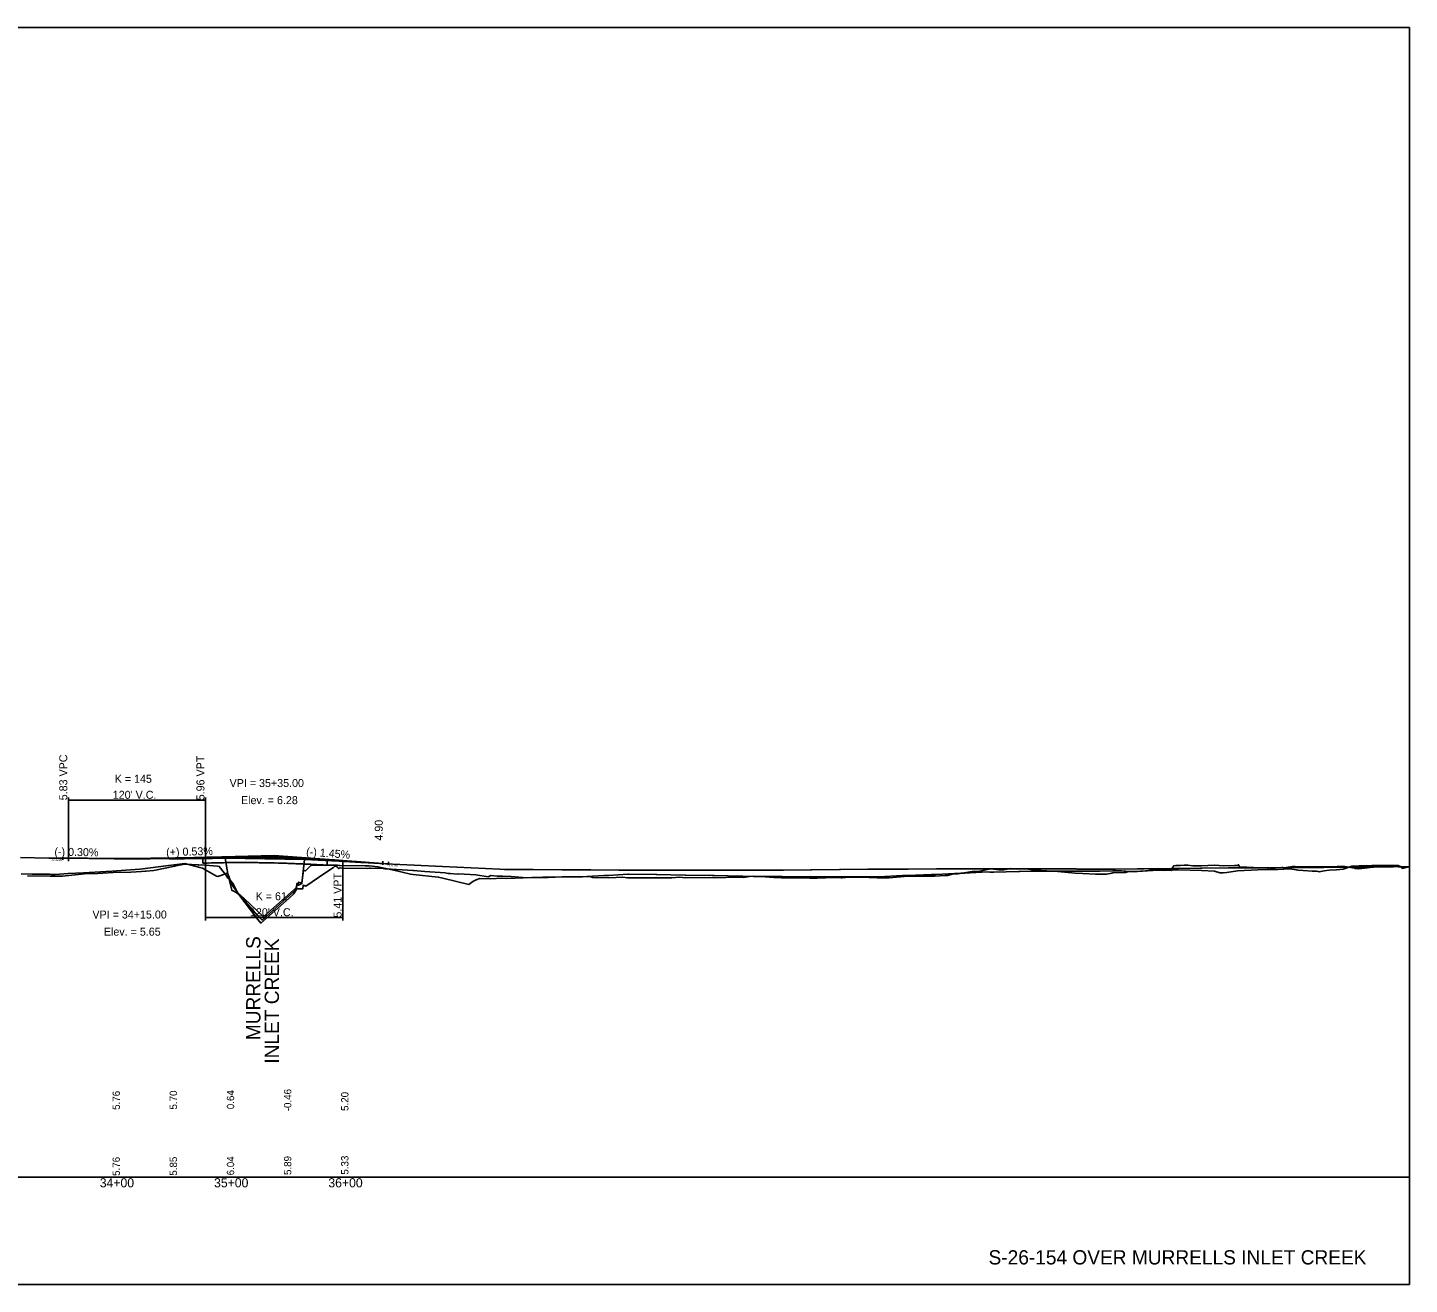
# Model space of a CAD drawing. Extents: x 2615579 to 2617675, y 643161 to 644261.
# Drawn here: x 2616466 to 2617675, y 643161 to 644261 of the extents above; entities that cross this region are included whole.
import ezdxf

# ---------------------------------------------------------------- set-up
doc = ezdxf.new("R2010")
doc.units = 0
for name, color, linetype in [('BR_CONCRETE', 7, 'Continuous'), ('BR_EXIST_GROUND_RT', 7, 'Continuous'), ('RD_EX_TX_Road_ELEV', 7, 'Continuous'), ('RD_PD_CstnLmt', 7, 'Continuous'), ('RD_PD_DR_ErosCtrl', 7, 'Continuous'), ('RD_PD_Final_TrvlWay', 7, 'Continuous'), ('RD_PD_PaveShd', 7, 'Continuous'), ('RD_PD_RW_TX', 7, 'Continuous'), ('RD_SHT_IplotShp', 7, 'Continuous'), ('RD_SHT_ShtClip', 7, 'Continuous'), ('RD_SHT_TX', 7, 'Continuous'), ('RD_Sketch8', 7, 'Continuous')]:
    doc.layers.add(name, color=color, linetype=linetype)

msp = doc.modelspace()

# ---------------------------------------------------------------- linework, layer by layer
at = {"layer": 'BR_CONCRETE'}
for p, q in [((2616619.3, 643529.3), (2616619.3, 643534.3)), ((2616728.2, 643527.5), (2616728.2, 643532.5))]:
    msp.add_line(p, q, dxfattribs=at)
msp.add_lwpolyline([(2616459.8, 643534.2), (2616484.8, 643533.7), (2616490, 643533.6), (2616514.6, 643533.5), (2616515, 643533.5), (2616539.4, 643533.3), (2616540, 643533.3), (2616564.3, 643533.2), (2616565, 643533.2), (2616565.6, 643533.2), (2616590, 643533.1), (2616602.4, 643533), (2616602.8, 643533), (2616603.4, 643533), (2616627.8, 643533.4), (2616633.8, 643533.5), (2616639, 643533.6), (2616640.6, 643523.4), (2616641.3, 643519.8), (2616643.5, 643513.6), (2616645.7, 643509.1), (2616649.5, 643504.3), (2616650.3, 643502.7), (2616667.6, 643483.1), (2616671.4, 643479.5), (2616692.6, 643498.5), (2616700.2, 643505.2), (2616700.5, 643506), (2616701.6, 643509.7), (2616703, 643510.1), (2616706.1, 643511.4), (2616708.4, 643532.5), (2616732.3, 643531.3), (2616733.3, 643531.2), (2616757.7, 643529.9), (2616758.3, 643529.9), (2616758.9, 643529.9), (2616779.3, 643528.8), (2616804.2, 643527.6), (2616829.2, 643526.4), (2616854.2, 643525.1), (2616879.1, 643523.9), (2616883.4, 643523.7), (2616888.4, 643523.7), (2616908.5, 643523.6), (2616933.6, 643523.5), (2616958.4, 643523.3), (2616958.8, 643523.3), (2616983.4, 643523.2), (2616991.3, 643523.2), (2617015.6, 643523.1), (2617016.3, 643523.1), (2617040.5, 643523.1), (2617041.3, 643523.1), (2617065.4, 643523), (2617066.3, 643523), (2617090.3, 643523), (2617091.3, 643523), (2617100.8, 643523), (2617101.3, 643523), (2617102.4, 643523), (2617126.3, 643523.2), (2617127.3, 643523.2), (2617151.3, 643523.4), (2617152.3, 643523.4), (2617176.3, 643523.7), (2617177.3, 643523.7), (2617201.3, 643523.9), (2617201.7, 643523.9), (2617211.4, 643524), (2617235.8, 643524.1), (2617236.4, 643524.1), (2617261.4, 643524.2), (2617266.4, 643524.2), (2617286.5, 643524.2), (2617307.9, 643524.2), (2617308.5, 643524.3), (2617309.1, 643524.3), (2617333.2, 643524.3), (2617334.1, 643524.3), (2617358.4, 643524.3), (2617359.4, 643524.2), (2617383.4, 643524.2), (2617384.5, 643524.1), (2617408.4, 643524.1), (2617408.7, 643524.1), (2617417.9, 643524.1), (2617437.2, 643524.3), (2617441.6, 643524.3), (2617442.9, 643524.3), (2617466.6, 643524.6), (2617467.9, 643524.6), (2617468.4, 643524.6), (2617492.2, 643524.9), (2617493.5, 643524.9), (2617516.9, 643525.1), (2617518.1, 643525.2), (2617524.9, 643525.2), (2617526.4, 643525.2), (2617549.9, 643525.3), (2617550.9, 643525.3), (2617574.8, 643525.4), (2617575.5, 643525.5), (2617599.8, 643525.6), (2617600.2, 643525.6), (2617625, 643525.7), (2617634, 643525.7), (2617636, 643525.7), (2617661, 643526.1), (2617675, 643526.3)], dxfattribs=at)
for points in [[(2616619.3, 643529.3), (2616619.5, 643529.3), (2616621.9, 643529.3)], [(2616621.9, 643529.3), (2616624.3, 643529.4), (2616626.7, 643529.4), (2616629.1, 643529.5), (2616631.5, 643529.5), (2616633.9, 643529.6), (2616636.3, 643529.6), (2616638.7, 643529.7), (2616641.1, 643529.7), (2616643.5, 643529.7), (2616645.9, 643529.7), (2616648.2, 643529.7), (2616650.6, 643529.7), (2616653, 643529.7), (2616655.4, 643529.7), (2616657.8, 643529.7), (2616660.2, 643529.7), (2616662.6, 643529.7), (2616665, 643529.7), (2616667.4, 643529.7), (2616669.8, 643529.6), (2616672.1, 643529.6), (2616674.5, 643529.6), (2616676.9, 643529.5), (2616679.3, 643529.5), (2616681.7, 643529.4), (2616684.1, 643529.4), (2616686.5, 643529.3), (2616688.9, 643529.2), (2616691.3, 643529.2), (2616693.7, 643529.1), (2616696, 643529), (2616698.4, 643528.9), (2616700.8, 643528.8), (2616703.2, 643528.7), (2616705.6, 643528.6), (2616708, 643528.5), (2616710.4, 643528.4), (2616712.8, 643528.3), (2616715.2, 643528.2), (2616717.6, 643528.1), (2616719.9, 643527.9), (2616722.3, 643527.8), (2616724.7, 643527.7), (2616727.1, 643527.5), (2616728.2, 643527.5)]]:
    msp.add_spline(points, degree=3, dxfattribs=at)
at = {"layer": 'BR_EXIST_GROUND_RT'}
msp.add_lwpolyline([(2616460.4, 643520), (2616470.1, 643519.7), (2616485.4, 643519.5), (2616487.1, 643519.4), (2616490.1, 643519.4), (2616501.6, 643520.1), (2616514.9, 643520.7), (2616534.7, 643522.1), (2616539.8, 643522.3), (2616564.4, 643524), (2616564.7, 643524.1), (2616589.4, 643527.1), (2616589.7, 643527.2), (2616603.5, 643528.9), (2616616.9, 643525.4), (2616619, 643524.9), (2616631.4, 643518), (2616632.5, 643517.7), (2616640, 643520.2), (2616641, 643520.9), (2616644.7, 643505.6), (2616649, 643503.4), (2616650.8, 643501.7), (2616667.5, 643479.8), (2616670.2, 643476.7), (2616694.8, 643498.5), (2616699, 643502.3), (2616699.3, 643503.1), (2616700.7, 643505.4), (2616702.5, 643507.1), (2616702.8, 643506.9), (2616704.4, 643506.9), (2616705.7, 643506.7), (2616706.9, 643506.9), (2616707.1, 643509.9), (2616709.5, 643509.2), (2616726, 643520.5), (2616733.6, 643525.5), (2616734.8, 643526.5), (2616736.2, 643526.4), (2616736.6, 643526), (2616737.4, 643525.4), (2616737.9, 643524.8), (2616738.3, 643524.6), (2616738.6, 643524.6), (2616739.4, 643525.3), (2616740.9, 643525), (2616763.7, 643524.7), (2616765.2, 643524.9), (2616766, 643524.9), (2616777.3, 643524.7), (2616778.7, 643524.4), (2616779.4, 643524.4), (2616803.2, 643522.8), (2616803.7, 643522.8), (2616813.6, 643522.1), (2616831.4, 643520.7), (2616832.6, 643520.5), (2616834, 643520.3), (2616835.8, 643520.3), (2616842, 643519.7), (2616843.1, 643519.8), (2616858.2, 643519), (2616868.9, 643517.3), (2616871.5, 643518.6), (2616877, 643518), (2616881.6, 643517.8), (2616889.1, 643517.5), (2616902.5, 643516.3), (2616921.5, 643516.7), (2616927.6, 643517), (2616933.6, 643517.2), (2616951.7, 643517.3), (2616958.3, 643517.7), (2616960.7, 643516.8), (2616974.6, 643516.4), (2616981.1, 643516.8), (2616986.7, 643517), (2616991, 643516.5), (2616999.9, 643516.4), (2617014.8, 643516.4), (2617015.5, 643516.4), (2617029.8, 643516.5), (2617036.4, 643516.9), (2617041.8, 643516.3), (2617062.4, 643516.6), (2617066.9, 643516.5), (2617087.3, 643516.9), (2617092.4, 643516.8), (2617097.6, 643517.7), (2617100.9, 643517.8), (2617107.7, 643517.7), (2617119, 643516.7), (2617125.6, 643516.5), (2617131.2, 643516.4), (2617150.5, 643516.1), (2617156.8, 643516), (2617171.5, 643516.6), (2617177.9, 643516.5), (2617178.7, 643516.5), (2617184.5, 643517), (2617202.5, 643516.7), (2617203.5, 643516.7), (2617209.5, 643516.3), (2617211.7, 643516.4), (2617219.9, 643516.4), (2617233.1, 643517.5), (2617239.8, 643517.9), (2617258.3, 643517.8), (2617259.4, 643517.9), (2617269, 643518.4), (2617271, 643518.4), (2617276.3, 643519.9), (2617280.3, 643520), (2617294.3, 643522.2), (2617296.6, 643522.1), (2617299, 643522.3), (2617308.7, 643524.3), (2617315.9, 643523.3), (2617320.1, 643523.4), (2617326.3, 643524.7), (2617331.5, 643523.9), (2617338.6, 643524.2), (2617355.9, 643522.4), (2617357.9, 643522.5), (2617367.5, 643522.1), (2617382.7, 643520.6), (2617389, 643520.1), (2617400.4, 643519.6), (2617406.1, 643519.5), (2617409.9, 643519.5), (2617414.7, 643520.6), (2617415.5, 643520.7), (2617425.1, 643521.1), (2617426.7, 643521.1), (2617427.5, 643521.4), (2617429.9, 643521.9), (2617434, 643522), (2617437.2, 643522.1), (2617439.8, 643522.3), (2617440.7, 643522.2), (2617444.2, 643522.6), (2617449.5, 643523.4), (2617455.3, 643523), (2617460.1, 643522.9), (2617466.1, 643523), (2617466.8, 643522.8), (2617468.2, 643525.8), (2617468.8, 643527), (2617470.7, 643527.1), (2617473.5, 643527.2), (2617474.6, 643527.2), (2617478, 643527.6), (2617481.2, 643527.4), (2617485.6, 643527), (2617487, 643527), (2617492.9, 643527), (2617504.6, 643527.4), (2617512.6, 643527), (2617521.9, 643527.3), (2617524.7, 643527.1), (2617525.6, 643527.8), (2617526.1, 643526.5), (2617526.5, 643525.7), (2617529.2, 643525.7), (2617532.9, 643525.7), (2617550.5, 643524.9), (2617551.2, 643524.9), (2617551.8, 643524.9), (2617563.3, 643525.6), (2617564.2, 643525.6), (2617565.3, 643525.3), (2617572.7, 643526.4), (2617573.5, 643526.2), (2617575.2, 643526.2), (2617593.5, 643525.9), (2617604.3, 643526.1), (2617611.7, 643526.3), (2617616.7, 643526.6), (2617625.3, 643525.1), (2617627.2, 643525.2), (2617627.9, 643524.4), (2617630.1, 643524.5), (2617630.8, 643524.4), (2617643.2, 643525.8), (2617643.9, 643525.9), (2617644.3, 643526), (2617646.3, 643526.3), (2617647.5, 643527.2), (2617648.7, 643527.2), (2617650.3, 643527.1), (2617655.7, 643527.2), (2617658.5, 643527.3), (2617662.2, 643527.3), (2617663.7, 643527.3), (2617665.2, 643527.2), (2617666.5, 643526.7), (2617668.1, 643525.9), (2617668.8, 643524.6), (2617674.1, 643526.1), (2617675, 643526.1)], dxfattribs=at)
at = {"layer": 'RD_EX_TX_Road_ELEV'}
msp.add_line((2615661.7, 643254.5), (2617675, 643254.5), dxfattribs=at)
at = {"layer": 'RD_PD_DR_ErosCtrl'}
msp.add_line((2616741.8, 643531.6), (2616776.8, 643529), dxfattribs=at)
for points in [[(2616501.8, 643533.7), (2616504.2, 643533.6), (2616506.6, 643533.6), (2616509, 643533.6), (2616511.4, 643533.5), (2616513.8, 643533.5), (2616516.2, 643533.5), (2616518.6, 643533.5), (2616521, 643533.4), (2616523.4, 643533.4), (2616525.8, 643533.4), (2616528.2, 643533.4), (2616530.6, 643533.4), (2616533, 643533.4), (2616535.4, 643533.3), (2616537.8, 643533.3), (2616540.2, 643533.3), (2616542.6, 643533.3), (2616545, 643533.3), (2616547.4, 643533.3), (2616549.8, 643533.3), (2616552.2, 643533.3), (2616554.6, 643533.3), (2616557, 643533.4), (2616559.4, 643533.4), (2616561.8, 643533.4), (2616564.2, 643533.4), (2616566.6, 643533.4), (2616569, 643533.4), (2616571.4, 643533.4), (2616573.8, 643533.5), (2616576.2, 643533.5), (2616578.6, 643533.5), (2616581, 643533.5), (2616583.4, 643533.6), (2616585.8, 643533.6), (2616588.2, 643533.6), (2616590.6, 643533.7), (2616593, 643533.7), (2616595.4, 643533.8), (2616597.8, 643533.8), (2616600.2, 643533.8), (2616602.6, 643533.9), (2616605, 643533.9), (2616607.4, 643534), (2616609.8, 643534), (2616612.2, 643534.1), (2616614.6, 643534.2), (2616617, 643534.2), (2616619.4, 643534.3), (2616621.8, 643534.3)], [(2616621.8, 643534.3), (2616624.2, 643534.4), (2616626.6, 643534.4), (2616629, 643534.5), (2616631.4, 643534.5), (2616633.8, 643534.6), (2616636.2, 643534.6), (2616638.6, 643534.7), (2616641, 643534.7), (2616643.4, 643534.7), (2616645.8, 643534.7), (2616648.2, 643534.7), (2616650.6, 643534.7), (2616653, 643534.7), (2616655.4, 643534.7), (2616657.8, 643534.7), (2616660.2, 643534.7), (2616662.6, 643534.7), (2616665, 643534.7), (2616667.4, 643534.7), (2616669.8, 643534.6), (2616672.2, 643534.6), (2616674.6, 643534.6), (2616677, 643534.5), (2616679.4, 643534.5), (2616681.8, 643534.4), (2616684.2, 643534.4), (2616686.6, 643534.3), (2616689, 643534.2), (2616691.4, 643534.2), (2616693.8, 643534.1), (2616696.2, 643534), (2616698.6, 643533.9), (2616701, 643533.8), (2616703.4, 643533.7), (2616705.8, 643533.6), (2616708.2, 643533.5), (2616710.6, 643533.4), (2616713, 643533.3), (2616715.4, 643533.2), (2616717.8, 643533.1), (2616720.2, 643532.9), (2616722.6, 643532.8), (2616725, 643532.7), (2616727.4, 643532.5), (2616729.8, 643532.4), (2616732.2, 643532.2), (2616734.6, 643532.1), (2616737, 643531.9), (2616739.4, 643531.7), (2616741.8, 643531.6)]]:
    msp.add_spline(points, degree=3, dxfattribs=at)
at = {"layer": 'RD_PD_RW_TX'}
msp.add_lwpolyline([(2616466, 643518.2), (2616485.8, 643517.9), (2616486.8, 643517.9), (2616491, 643517.8), (2616496.6, 643518), (2616515.9, 643519.8), (2616527.6, 643520.1), (2616540.8, 643521.2), (2616556.5, 643521.5), (2616565.7, 643522.1), (2616568.9, 643522.2), (2616569.8, 643522.3), (2616576.4, 643522.9), (2616595, 643526.7), (2616595.7, 643526.8), (2616603.4, 643528.5), (2616604, 643528.5), (2616615.2, 643527.9), (2616616, 643527.6), (2616617.9, 643527.9), (2616632.3, 643526.6), (2616633.8, 643526.4), (2616638.2, 643520.7), (2616638.6, 643520.4), (2616641.3, 643516.2), (2616641.9, 643516.1), (2616645.9, 643511.3), (2616646.3, 643510.3), (2616649.7, 643503.5), (2616652.4, 643501.2), (2616655.7, 643498.2), (2616672.5, 643482.4), (2616674, 643483.8), (2616701.4, 643508.1), (2616701.7, 643511.5), (2616702, 643509.7), (2616702.7, 643510.4), (2616703.1, 643512.9), (2616703.3, 643512.1), (2616706.1, 643512.4), (2616707.4, 643522.7), (2616709.3, 643522.5), (2616713.8, 643527.3), (2616714.4, 643527.3), (2616720.8, 643527.5), (2616737.3, 643527.5), (2616738.6, 643527.3), (2616739.3, 643527.2), (2616761.3, 643527), (2616762.3, 643527), (2616765, 643526.9), (2616772.6, 643526.1), (2616779.4, 643524.5), (2616786.4, 643523), (2616801.1, 643519.5), (2616803.3, 643519.3), (2616825.3, 643517), (2616828, 643516.4), (2616829.5, 643516), (2616852, 643510.6), (2616855.7, 643513.2), (2616858.4, 643514.7), (2616861.8, 643515.8), (2616871.4, 643515.5), (2616881.1, 643516.1), (2616885.5, 643515.9), (2616907.2, 643516.8), (2616908.8, 643516.8), (2616916.8, 643517.1), (2616933.4, 643517.3), (2616943.7, 643517.4), (2616950.4, 643517.4), (2616970.1, 643518.5), (2616974.3, 643518.6), (2616991.2, 643519.7), (2616991.7, 643519.7), (2617015.6, 643519.3), (2617016.7, 643519.3), (2617041.2, 643518.8), (2617041.7, 643518.8), (2617065.1, 643518.4), (2617066.7, 643518.4), (2617091.4, 643517.9), (2617091.7, 643517.8), (2617101.1, 643517.6), (2617124.6, 643517.5), (2617126.2, 643517.5), (2617148.6, 643517.4), (2617151.2, 643517.5), (2617172.6, 643517.4), (2617176.3, 643517.4), (2617196.7, 643517.3), (2617201.3, 643517.4), (2617209, 643517.4), (2617210.9, 643517.4), (2617231.6, 643518.4), (2617235.9, 643518.4), (2617256.9, 643519.4), (2617260.8, 643519.3), (2617282.5, 643520.5), (2617285.8, 643520.4), (2617305.9, 643521.6), (2617308, 643521.4), (2617311.4, 643521.5), (2617333, 643522), (2617334.1, 643522.1), (2617343.2, 643522.3), (2617357.3, 643522.3), (2617358.1, 643522.3), (2617381.1, 643522.2), (2617383.1, 643522.2), (2617401.4, 643522.2), (2617404.2, 643522.3), (2617415.7, 643522.6), (2617417.6, 643522.6), (2617423, 643522.5), (2617434.8, 643521.8), (2617437.2, 643522), (2617459.3, 643523.3), (2617466.3, 643523.4), (2617473.1, 643523.4), (2617493.2, 643522.9), (2617504.4, 643522.3), (2617509.3, 643520.7), (2617512, 643520.8), (2617515.3, 643521.1), (2617524.7, 643522.5), (2617542.3, 643523.3), (2617552.8, 643523.7), (2617560, 643523.7), (2617570.3, 643524.2), (2617576, 643523.5), (2617577.6, 643523), (2617582.1, 643522.8), (2617590, 643522.3), (2617593.7, 643522.2), (2617595.4, 643521.9), (2617596.2, 643521.8), (2617597.4, 643521.9), (2617600.4, 643522.4), (2617604.9, 643523.1), (2617611.2, 643523.5), (2617617.2, 643524.1), (2617624.6, 643526.5), (2617637.1, 643527.1), (2617641.1, 643527), (2617642.3, 643527.1), (2617648.1, 643527.3), (2617655.8, 643527.3), (2617662, 643526.5), (2617666.9, 643525.7), (2617673.1, 643526)], dxfattribs=at)
at = {"layer": 'RD_SHT_IplotShp'}
for p, q in [((2616501.8, 643533.7), (2616561.8, 643532.8)), ((2616641.8, 643534.9), (2616561.8, 643532.8)), ((2616601.8, 643533.8), (2616681.8, 643535.9)), ((2616761.6, 643530.1), (2616681.8, 643535.9))]:
    msp.add_line(p, q, dxfattribs=at)
at = {"layer": 'RD_SHT_ShtClip'}
for p, q in [((2616496.8, 643534.5), (2616496.8, 643532.3)), ((2616496.8, 643533.6), (2616501.8, 643533.6)), ((2616501.8, 643535.4), (2616501.8, 643530.9)), ((2616501.8, 643533.6), (2616501.8, 643533.7)), ((2616619.3, 643533.4), (2616619.3, 643534.3)), ((2616639, 643534.6), (2616708.4, 643533.4)), ((2616639, 643533.7), (2616639, 643534.6)), ((2616639, 643533.6), (2616639, 643533.7)), ((2616708.4, 643532.5), (2616639, 643533.6)), ((2616708.4, 643532.6), (2616708.4, 643533.4)), ((2616708.4, 643532.5), (2616708.4, 643532.6)), ((2616728.2, 643531.6), (2616728.2, 643532.5)), ((2616776.8, 643531.1), (2616776.8, 643527.8)), ((2616776.8, 643528.9), (2616776.8, 643529)), ((2616776.8, 643528.9), (2616781.8, 643528.7)), ((2616781.8, 643530.3), (2616781.8, 643527.7)), ((2616796.8, 643528), (2616796.8, 643527.9))]:
    msp.add_line(p, q, dxfattribs=at)
msp.add_lwpolyline([(2615875, 644260.6), (2617675, 644260.6), (2617675, 643160.6), (2615875, 643160.6)], close=True, dxfattribs=at)
at = {"layer": 'RD_Sketch8'}
for p, q in [((2616501.8, 643586.8), (2616501.8, 643533.7)), ((2616501.8, 643584.3), (2616621.8, 643584.3)), ((2616621.8, 643586.8), (2616621.8, 643534.3)), ((2616621.8, 643479.1), (2616621.8, 643534.3)), ((2616741.8, 643479.1), (2616741.8, 643531.6)), ((2616621.8, 643481.6), (2616741.8, 643481.6))]:
    msp.add_line(p, q, dxfattribs=at)

# ---------------------------------------------------------------- texts
at = {"layer": 'RD_PD_CstnLmt'}
for s, p in [('34+00', (2616529.2, 643245.5)), ('35+00', (2616629.2, 643245.5)), ('36+00', (2616729.2, 643245.5))]:
    msp.add_text(s, height=8, dxfattribs=at).set_placement(p)
at = {"layer": 'RD_PD_Final_TrvlWay'}
for s, height, p in [('5.83 VPC', 7, (2616500.8, 643584.3)), ('5.96 VPT', 7, (2616620.8, 643584.3)), ('5.41 VPT', 7, (2616740.8, 643481.6)), ('5.76', 6.4, (2616546.8, 643313.3)), ('5.70', 6.4, (2616596.8, 643313.6)), ('0.64', 6.4, (2616646.8, 643313.9)), ('-0.46', 6.4, (2616696.8, 643312.1)), ('5.20', 6.4, (2616746.8, 643312.4)), ('5.76', 6.4, (2616546.8, 643255.5)), ('5.85', 6.4, (2616596.8, 643255.7)), ('6.04', 6.4, (2616646.8, 643256)), ('5.89', 6.4, (2616696.8, 643256.3)), ('5.33', 6.4, (2616746.8, 643256.6))]:
    msp.add_text(s, height=height, rotation=90, dxfattribs=at).set_placement(p)
at = {"layer": 'RD_PD_PaveShd'}
for s, p in [('VPI = 35+35.00', (2616642.8, 643595.9)), ('Elev. = 6.28', (2616652.8, 643580.9)), ('VPI = 34+15.00', (2616522.8, 643480.8)), ('Elev. = 5.65', (2616532.8, 643465.8))]:
    msp.add_text(s, height=7, dxfattribs=at).set_placement(p)
msp.add_text('4.90', height=7, rotation=90, dxfattribs=at).set_placement((2616776.8, 643549))
at = {"layer": 'RD_SHT_IplotShp'}
for s, rotation, p in [('(-) 0.30%', 359.1406, (2616489.5, 643535.8)), ('(+) 0.53%', 1.5048, (2616587.4, 643535.4)), ('(-) 1.45%', 355.8533, (2616709.6, 643535.9))]:
    msp.add_text(s, height=7, rotation=rotation, dxfattribs=at).set_placement(p)
at = {"layer": 'RD_SHT_ShtClip'}
for s, p in [('-0.1220', (2616487, 643531.2)), ('-1.0180', (2616780.8, 643526.1))]:
    msp.add_text(s, height=2, dxfattribs=at).set_placement(p)
at = {"layer": 'RD_SHT_TX'}
for s, height, rotation, p in [('MURRELLS', 12.5, 90, (2616669.8, 643374.3)), (' INLET CREEK', 12.5, 90, (2616686, 643349.1)), ('S-26-154 OVER MURRELLS INLET CREEK', 12.499, 360, (2617306.8, 643178))]:
    msp.add_text(s, height=height, rotation=rotation, dxfattribs=at).set_placement(p)
at = {"layer": 'RD_Sketch8'}
for s, p in [('K = 145', (2616542.3, 643599.6)), ("120' V.C.", (2616540.6, 643585.6)), ('K = 61', (2616665.6, 643496.8)), ("120' V.C.", (2616660.6, 643482.8))]:
    msp.add_text(s, height=7, dxfattribs=at).set_placement(p)

doc.saveas('drawing.dxf')
